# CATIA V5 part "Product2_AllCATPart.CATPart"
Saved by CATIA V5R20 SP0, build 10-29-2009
Part number: Product2_AllCATPart
Bounding box of the stored display mesh (mm): x -204 to 104, y 0 to 684, z -70 to 85
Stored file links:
  C:\Users\halimelbaba\Documents\cmv\final\Product2_AllCATPart.CATPart
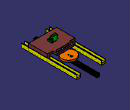
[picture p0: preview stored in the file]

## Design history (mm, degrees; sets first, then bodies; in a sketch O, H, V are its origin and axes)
Body1 (main body)
Body2 "table\\PartBody"
  Solid1: solid without history
Body3 "support de lame.1\\PartBody"
  Solid2 "Solid.1": solid without history
Body4 "support de lame2.1\\PartBody"
  Solid3 "Solid.1": solid without history
Body5 "poulie.1\\PartBody"
  Solid4 "Solid.1": solid without history
Body6 "maneton .1\\PartBody"
  Solid5 "Solid.1": solid without history
Body7 "barre\\MANIFOLD_SOLID_BREP #6353"
  Solid6 "Solid.1": solid without history
Body8 "axe de poulie.1\\PartBody"
  Solid7 "Solid.1": solid without history
Body9 "Rails.1\\PartBody"
  Solid8 "Solid.1": solid without history
Body10 "Rails.2\\PartBody"
  Solid9 "Solid.1": solid without history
